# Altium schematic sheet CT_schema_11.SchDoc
size 278 x 170 mm
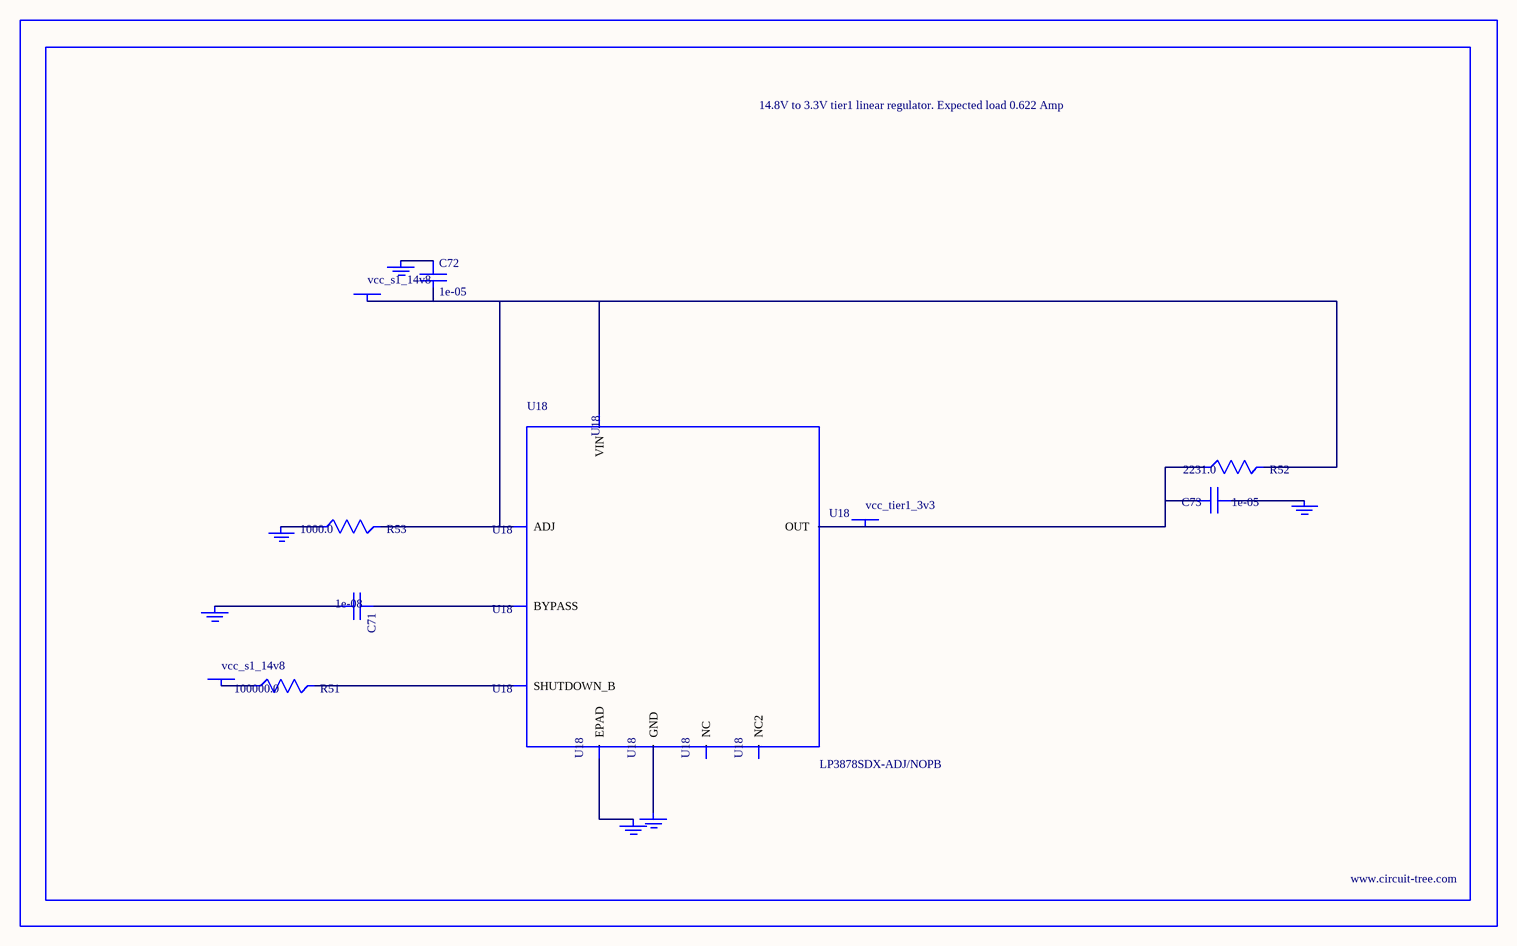
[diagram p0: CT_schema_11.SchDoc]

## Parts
BORDER10  (no value)
C71  1e-08  [C0402]
C72  1e-05  [C1210]
C73  1e-05  [C1210]
GND_INSTANCE_10_0  (no value)
GND_INSTANCE_10_1  (no value)
GND_INSTANCE_10_2  (no value)
GND_INSTANCE_10_3  (no value)
GND_INSTANCE_10_4  (no value)
GND_INSTANCE_10_5  (no value)
POWER_INSTANCE_10_0  vcc_s1_14v8
POWER_INSTANCE_10_1  vcc_s1_14v8
POWER_INSTANCE_10_2  vcc_tier1_3v3
R51  100000.0  [R0603]
R52  2231.0  [R0603]
R53  1000.0  [R0603]
U18  LP3878SDX-ADJ/NOPB  [WSON-8]

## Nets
NetC71_1: C71.1 U18.1(BYPASS)
NetC71_2: C71.2 GND_INSTANCE_10_0.0(GND)
NetC72_1: C72.1 GND_INSTANCE_10_1.0(GND)
NetC72_2: C72.2 POWER_INSTANCE_10_0.0(PWR) R52.2 R53.2 U18.4(VIN) U18.6(ADJ)
NetC73_1: C73.1 GND_INSTANCE_10_2.0(GND)
NetC73_2: C73.2 POWER_INSTANCE_10_2.0(PWR) R52.1 U18.5(OUT)
NetGND_INSTANCE_10_3_0: GND_INSTANCE_10_3.0(GND) R53.1
NetGND_INSTANCE_10_4_0: GND_INSTANCE_10_4.0(GND) U18.PAD(EPAD)
NetGND_INSTANCE_10_5_0: GND_INSTANCE_10_5.0(GND) U18.3(GND)
NetPOWER_INSTANCE_10_1_0: POWER_INSTANCE_10_1.0(PWR) R51.1
NetR51_2: R51.2 U18.8(SHUTDOWN_B)

Not connected (* = marked no-connect by the designer): U18 2(NC) 7(NC2)

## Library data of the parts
BORDER10 = BORDER_PAGE10
C71 = C0402C103K3RAC
C72 = C1210C106K5PACTU
C73 = GRM32DR61E106MA12L
GND_INSTANCE_10_0-GND_INSTANCE_10_5 = GND
POWER_INSTANCE_10_0-POWER_INSTANCE_10_2 = PWR
R51 = RC0603JR-07100KL
R52 = R52
R53 = RC0603JR-071KL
